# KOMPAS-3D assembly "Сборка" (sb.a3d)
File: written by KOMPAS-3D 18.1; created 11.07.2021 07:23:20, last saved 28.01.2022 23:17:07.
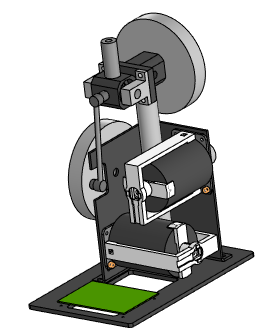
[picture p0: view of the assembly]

Document properties: Автор: 111; Полное имя файла: C:\Users\admin\Desktop\ffb\sb.a3d

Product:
- Part/product: Сборка
    Масса: 11.7967
  - Component [standard]: Подшипник 80201 ГОСТ 7242-81  | pos. 22  | Масса: 0.037; Раздел спецификации: Стандартные изделия; Рассекать на разрезах: no; additional columns: 80201
  - Component [standard]: Подшипник 80201 ГОСТ 7242-81  | pos. 1  | Масса: 0.037; Раздел спецификации: Стандартные изделия; Рассекать на разрезах: no; additional columns: 80201
  - Component [detail]: Деталь  | pos. 10  | Масса: 1.10029; Раздел спецификации: Детали; source file: p1.m3d
  - Component [detail]: Деталь  | pos. 4  | Масса: 1.75922; Раздел спецификации: Детали; source file: 4.m3d
  - Component [detail]: Деталь  | pos. 19  | Масса: 0.0864121; Раздел спецификации: Детали; Форматы листов документа: A4; source file: ..\4.cdw, Lii.m3d
  - Component [detail]: Деталь  | pos. 5  | Масса: 0.194146; Раздел спецификации: Детали; Форматы листов документа: A4; source file: ..\1.cdw, 6.cdw, D.m3d
  - Component [detail]: Деталь  | pos. 16  | Раздел спецификации: Детали; source file: t.m3d
  - Component [detail]: Деталь  | pos. 17  | Масса: 0.0808172; Раздел спецификации: Детали; source file: 11.m3d
  - Component [detail]: Деталь  | pos. 20  | Масса: 0.0808172; Раздел спецификации: Детали; source file: 11.m3d
  - Component [detail]: Деталь  | pos. 14  | Масса: 0.0680655; Раздел спецификации: Детали; Форматы листов документа: A4; source file: 10.m3d, 5.cdw
  - Component [detail]: Деталь  | pos. 8  | Масса: 0.194146; Раздел спецификации: Детали; Форматы листов документа: A4; source file: ..\1.cdw, 6.cdw, D.m3d
  - Component [detail]: Деталь  | pos. 13  | Масса: 1.75922; Раздел спецификации: Детали; source file: 4.m3d
  - Component [detail]: Деталь  | pos. 21  | Масса: 0.0864121; Раздел спецификации: Детали; Форматы листов документа: A4; source file: ..\4.cdw, Lii.m3d
  - Component [detail]: Деталь  | pos. 6  | Масса: 0.345327; Раздел спецификации: Детали; Форматы листов документа: A4; source file: ..\10.cdw, 5.m3d
  - Component [detail]: Деталь  | pos. 9  | Масса: 0.647503; Раздел спецификации: Детали; source file: 23.m3d
  - Component [detail]: Деталь  | pos. 12  | Масса: 0.0888493; Раздел спецификации: Детали; source file: l.m3d
  - Component [detail]: Деталь  | pos. 15  | Масса: 0.0888493; Раздел спецификации: Детали; source file: l.m3d
  - Component [detail]: Деталь  | pos. 25  | Масса: 0.212612; Раздел спецификации: Детали; Форматы листов документа: A4; source file: 2.m3d, 7.cdw
  - Component [detail]: Деталь  | pos. 26  | Раздел спецификации: Детали; Форматы листов документа: A4; source file: ..\9.cdw, 9.cdw, 9.m3d
  - Component [detail]: Деталь  | pos. 27  | Масса: 0.198381; Раздел спецификации: Детали; source file: s1.m3d
  - Component [assembly]: Сборка  | pos. 31  | Масса: 2.28522; Раздел спецификации: Сборочные единицы; source file: мтр.a3d
  - Component [assembly]: Сборка  | pos. 32  | Масса: 2.28522; Раздел спецификации: Сборочные единицы; source file: мтр.a3d
  - Component [detail]: Деталь  | pos. 33  | Масса: 0.0854733; Раздел спецификации: Детали; source file: plata.m3d
  - Body: Тело 4
      Масса: 0.0240387
  - Body: Тело 5
      Масса: 0.0279382
  - Component [detail]: Деталь  | pos. 34  | Масса: 0.0237672; Раздел спецификации: Детали; source file: 8.m3d

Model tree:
1. Эскиз:1  (with: Элемент выдавливания:1, Элемент выдавливания:4)
2. Элемент выдавливания:1
     Расстояние 1 = 10
3. Эскиз:2  (with: Элемент выдавливания:1, Элемент выдавливания:4)
4. Элемент выдавливания:2  (with: Элемент выдавливания:6, Элемент выдавливания:1, Элемент выдавливания:5, Элемент выдавливания:3, Листовое тело:2)
     Расстояние 1 = 10; Ориентация = 2; Ориентация = 2

Referenced files in C:\Users\admin\Desktop\ffb\: 4.m3d, D.m3d, 6.cdw, 5.m3d, 23.m3d, p1.m3d, l.m3d, 10.m3d, 5.cdw, t.m3d, 11.m3d, Lii.m3d, 2.m3d, 7.cdw, 9.m3d, 9.cdw, s1.m3d, мтр.a3d, plata.m3d, 8.m3d
Referenced files in C:\Users\admin\Desktop\ffb\..\: 1.cdw, 10.cdw, 4.cdw, 9.cdw
Referenced files in C:\Program Files\ASCON\KOMPAS-3D v18\Libs\PartLib\DATA\VAULT\methods\kompas\3d\Bearings\7242_81\: PLib_Bearing_GOST_7242_81_712.a3d
Referenced files in C:\Users\admin\Desktop\KOMPAS\: 11.m3d, Lii.m3d, 4.m3d
Referenced files in C:\Users\admin\Desktop\Новая папка (2)\: l.m3d
Referenced files in C:\Program Files\ASCON\KOMPAS-3D v18\Libs\PARTLib\DATA\vault\Methods\Kompas\3D\Bearings\7242_81\: PLib_Bearing_GOST_7242_81_712.a3d
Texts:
  Деталь (1)
  Деталь (2)
  Подшипник 80201 ГОСТ 7242-81 (1)
  Ring1
  Ring2
  Подшипник 80201 ГОСТ 7242-81 (2)
  Сборка (1)
  Сборка (2)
